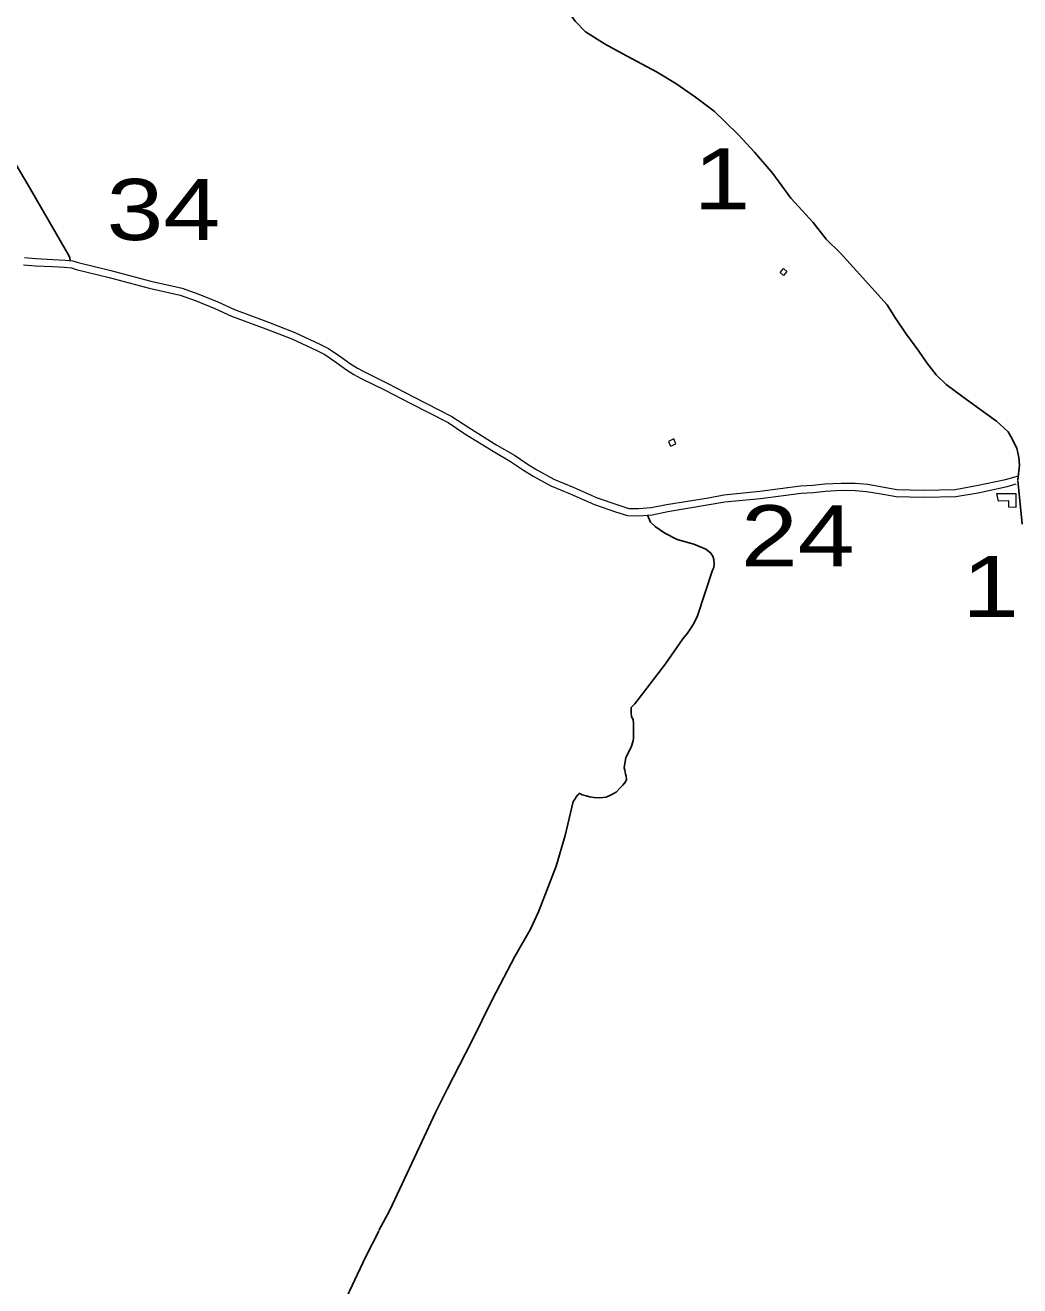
# Model space of a CAD drawing. Extents: x 476989 to 498418, y 4381813 to 4416555.
# Drawn here: x 485600 to 486413, y 4386800 to 4387830 of the extents above; entities that cross this region are included whole.
import ezdxf
from ezdxf.enums import TextEntityAlignment as Align

# ---------------------------------------------------------------- set-up
doc = ezdxf.new("R2010")
doc.units = 0
doc.header["$LTSCALE"] = 20
doc.linetypes.add('MEDIUM_DASHED', pattern=[4.5, 3, -1.5])
for name, color, linetype, lineweight in [('13', 7, 'Continuous', 13), ('36', 7, 'Continuous', 13), ('47', 7, 'Continuous', 13), ('48', 7, 'MEDIUM_DASHED', 13), ('6', 7, 'Continuous', 25)]:
    doc.layers.add(name, color=color, linetype=linetype, lineweight=lineweight)

msp = doc.modelspace()

# ---------------------------------------------------------------- linework, layer by layer
at = {"layer": '36'}
for points in [[(485599.42, 4387640.44), (485608.78, 4387639.71), (485622.5, 4387638.98), (485632.69, 4387638.46), (485639.02, 4387637.77), (485643.14, 4387636.43), (485670.12, 4387629.89), (485702.71, 4387621.09), (485728.3, 4387615.4), (485741.97, 4387610.63), (485757.5, 4387604.24), (485770.99, 4387598.04), (485798.82, 4387587.68), (485820.32, 4387579.33), (485840.91, 4387569.8), (485847.92, 4387566.17), (485858.19, 4387559.27), (485865.91, 4387553.53), (485871.63, 4387550.07), (485877.42, 4387546.92), (485896.42, 4387537.64), (485917.43, 4387526.69), (485948.87, 4387510.62), (485962.71, 4387501.42), (485985.53, 4387487.21), (485999.97, 4387478.82), (486010.53, 4387471.69), (486018.26, 4387466.93), (486032.24, 4387459.24), (486047.97, 4387452.71), (486067.73, 4387443.96), (486084.52, 4387438.16), (486093.46, 4387435.34), (486101.37, 4387435.15), (486111.95, 4387436.05), (486124.36, 4387438.5), (486158.65, 4387443.94), (486171.22, 4387446.53), (486200.61, 4387449.41), (486233.99, 4387453.74), (486244.06, 4387454.27), (486253.83, 4387455.33), (486267.28, 4387456.04), (486278.77, 4387455.87), (486288.75, 4387455.13), (486299.24, 4387453.26), (486312.7, 4387450.89), (486334.51, 4387450.35), (486360.31, 4387450.88), (486377.98, 4387454), (486401.45, 4387458.91), (486412.26, 4387462.09)], [(485598.66, 4387634.6), (485608.4, 4387633.84), (485622.19, 4387633.11), (485632.22, 4387632.6), (485637.78, 4387631.99), (485641.54, 4387630.77), (485668.67, 4387624.2), (485701.31, 4387615.39), (485726.69, 4387609.74), (485739.89, 4387605.13), (485755.16, 4387598.85), (485768.73, 4387592.61), (485796.73, 4387582.18), (485818.02, 4387573.92), (485838.32, 4387564.52), (485844.92, 4387561.11), (485854.8, 4387554.47), (485862.63, 4387548.64), (485868.7, 4387544.98), (485874.73, 4387541.7), (485893.77, 4387532.39), (485914.74, 4387521.47), (485945.9, 4387505.54), (485959.53, 4387496.48), (485982.5, 4387482.18), (485996.85, 4387473.84), (486007.34, 4387466.75), (486015.3, 4387461.85), (486029.69, 4387453.94), (486045.65, 4387447.31), (486065.57, 4387438.48), (486082.67, 4387432.58), (486092.49, 4387429.48), (486101.55, 4387429.27), (486112.77, 4387430.22), (486125.48, 4387432.73), (486172.11, 4387440.71), (486201.27, 4387443.57), (486234.53, 4387447.88), (486244.53, 4387448.41), (486254.3, 4387449.47), (486267.39, 4387450.16), (486278.51, 4387450), (486288.02, 4387449.29), (486298.22, 4387447.47), (486312.11, 4387445.02), (486334.5, 4387444.47), (486360.89, 4387445.01), (486379.09, 4387448.22), (486402.88, 4387453.21), (486410.26, 4387455.38)]]:
    msp.add_lwpolyline(points, dxfattribs=at)
at = {"layer": '47'}
msp.add_lwpolyline([(486394.5, 4387447.43), (486409.96, 4387447.66), (486410.13, 4387436.18), (486404.24, 4387436.34), (486404.37, 4387441.42), (486395.98, 4387441.26)], close=True, dxfattribs=at)
at = {"layer": '48'}
for points in [[(486222.79, 4387629), (486220.04, 4387625.87), (486217.23, 4387628.33), (486219.98, 4387631.46)], [(486125.88, 4387490.15), (486127.64, 4387486.28), (486132, 4387488.26), (486130.24, 4387492.13)]]:
    msp.add_lwpolyline(points, close=True, dxfattribs=at)
at = {"layer": '6'}
for points in [[(485912.17, 4388011.78), (485935.61, 4387985.33), (485960.06, 4387956.84), (485983.16, 4387928.35), (486007.28, 4387896.47), (486027.88, 4387862.88), (486044.27, 4387841.38), (486049.75, 4387833.89), (486058.02, 4387825.05), (486074.09, 4387815.1), (486088.73, 4387807.17), (486116.23, 4387792.4)], [(486116.23, 4387792.4), (486132.03, 4387782.95), (486147.96, 4387771.75), (486163.27, 4387760.17), (486172.57, 4387751.14), (486183, 4387741), (486196.38, 4387726.7), (486211.2, 4387709.12), (486226.06, 4387689.1), (486244.26, 4387669.22), (486254.87, 4387655.62), (486266.52, 4387644.16), (486282.31, 4387626.78), (486304.74, 4387601.82), (486311.03, 4387591.7), (486319.95, 4387578.44), (486330.78, 4387563.95), (486337.26, 4387554.38), (486344.84, 4387544.52), (486353.11, 4387536.82), (486365.48, 4387527.49), (486378.58, 4387517.9), (486394.08, 4387506.62), (486403.68, 4387498.03), (486406.02, 4387494.04)], [(485553.28, 4387782.16), (485574.6, 4387746.28), (485602.45, 4387699.59), (485635.65, 4387642.16), (485636.43, 4387640.27), (485636.65, 4387638.03)], [(486406.02, 4387494.04), (486410.83, 4387484.53), (486412.59, 4387477.02), (486412.95, 4387470.73), (486411.61, 4387458.73)], [(486411.61, 4387458.24), (486415.3, 4387422.43)], [(486108.72, 4387429.88), (486111.15, 4387424.2), (486115.09, 4387420.58), (486123.07, 4387414.99), (486132.97, 4387410.05), (486146.69, 4387406.04), (486156.54, 4387401.92), (486160.35, 4387399.14), (486162.24, 4387396.44), (486163.03, 4387393.52), (486163.22, 4387390.05), (486163.01, 4387387.04), (486162.1, 4387384.84), (486149.71, 4387347.62), (486147.02, 4387341.86), (486144.83, 4387338.28), (486141.42, 4387333.4), (486137.75, 4387328.8), (486123.51, 4387308.31), (486098.49, 4387275.55)], [(486098.49, 4387275.55), (486095.45, 4387272.46), (486095.42, 4387270.58), (486095.4, 4387269.3), (486095.39, 4387268.63), (486095.81, 4387264.82)], [(485889.1, 4386844.91), (485898.22, 4386861.52), (485924.32, 4386917.39), (485935.38, 4386941.3), (485945.1, 4386960.49), (485965.17, 4386999.61), (485982.1, 4387034.09), (486000.35, 4387068.9), (486013.22, 4387091.19), (486019.79, 4387105.48), (486034.18, 4387142.83), (486041.39, 4387167.75), (486048.03, 4387195.58), (486049.73, 4387197.92), (486050.22, 4387198.85), (486051.3, 4387200.5), (486052.27, 4387201.5), (486053.26, 4387202.33), (486053.18, 4387202.28), (486052.94, 4387202.28), (486054.06, 4387201.94), (486055.28, 4387201.23), (486057.62, 4387200.6), (486058.76, 4387200.43), (486061.5, 4387199.5), (486065.29, 4387198.87), (486069.79, 4387198.81), (486074.96, 4387199.22), (486079.22, 4387201.03), (486083.33, 4387203.26), (486086.51, 4387206.74), (486088.66, 4387209.06), (486090.93, 4387211.75), (486091.67, 4387213.64), (486091.33, 4387216.29), (486090.88, 4387218.02), (486090.18, 4387221.36), (486089.63, 4387223.21), (486091.15, 4387231.55), (486095.34, 4387240.23), (486097, 4387245.29), (486097.29, 4387247.57), (486097.32, 4387249.61), (486097.36, 4387252.18), (486097.33, 4387255.71), (486097.39, 4387259.56), (486097, 4387262.75), (486096.29, 4387264.23), (486095.81, 4387264.86)], [(485772.9, 4386620.73), (485793.92, 4386659.02), (485816.04, 4386701.22), (485833.41, 4386729.64), (485844.8, 4386751.93), (485852.09, 4386767.68), (485860.52, 4386785.33), (485878.39, 4386823.62), (485889.18, 4386844.24)]]:
    msp.add_lwpolyline(points, dxfattribs=at)

# ---------------------------------------------------------------- texts
at = {"layer": '13', "width": 1.25}
for s, p in [('34', (485712.96, 4387654.82)), ('24', (486231.73, 4387387.95))]:
    msp.add_text(s, height=50, dxfattribs=at).set_placement(p, align=Align.CENTER)
at = {"layer": '6', "width": 1.25}
for p in [(486169.71, 4387679.88), (486389.45, 4387346.57)]:
    msp.add_text('1', height=50, dxfattribs=at).set_placement(p, align=Align.CENTER)

doc.saveas('drawing.dxf')
